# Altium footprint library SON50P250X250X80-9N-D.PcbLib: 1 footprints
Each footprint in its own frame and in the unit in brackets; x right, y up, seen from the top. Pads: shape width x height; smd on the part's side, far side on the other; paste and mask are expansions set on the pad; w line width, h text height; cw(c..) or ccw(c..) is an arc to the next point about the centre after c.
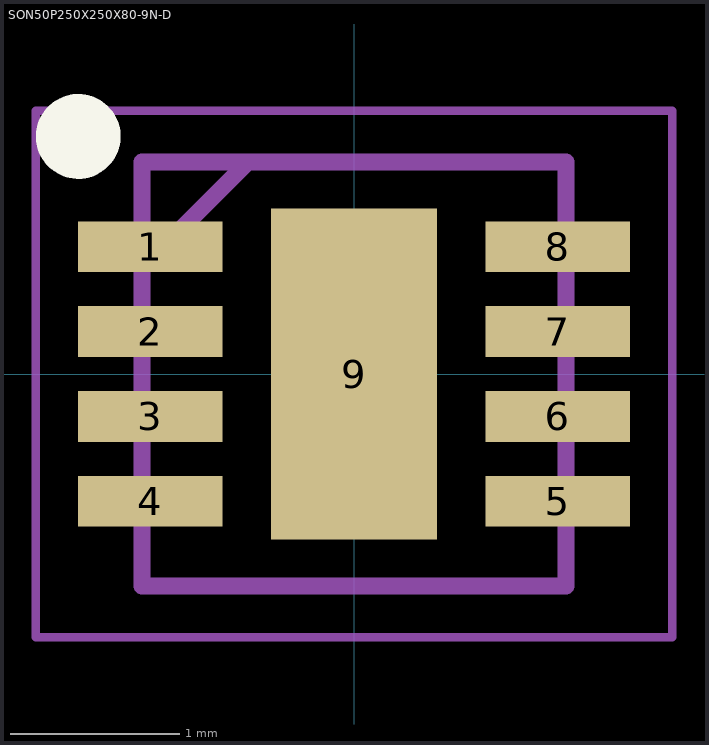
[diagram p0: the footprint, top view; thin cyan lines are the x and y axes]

## SON50P250X250X80-9N-D [mm]
pads (9):
  rect 0.85x0.3 smd: 1(-1.2,0.75) 2(-1.2,0.25) 3(-1.2,-0.25) 4(-1.2,-0.75) 5(1.2,-0.75) 6(1.2,-0.25) 7(1.2,0.25) 8(1.2,0.75)
  rect 0.98x1.95 smd: 9(0,0)
Top Overlay:
  circle w0.25: c-1.625,1.4 r0.125
Mechanical 15:
  lines w0.1: -1.25,0.625 -0.625,1.25 ; -1.25,-1.25 1.25,-1.25 1.25,1.25 -1.25,1.25 -1.25,-1.25
Mechanical 20:
  lines w0.05: -1.875,-1.55 1.875,-1.55 1.875,1.55 -1.875,1.55 -1.875,-1.55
